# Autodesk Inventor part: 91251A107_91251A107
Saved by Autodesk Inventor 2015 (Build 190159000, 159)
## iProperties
Created: 2014-11
Part Number: 91251A107_91251A107
Material: Generic
Document SubType Name: Modeling
Designer: User
Density: 1 g/cm^3
Appearance: Default
Author: User
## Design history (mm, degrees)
node "91251A107_91251A107.ipt1"
node "Chamfer1"
node "Base1"
